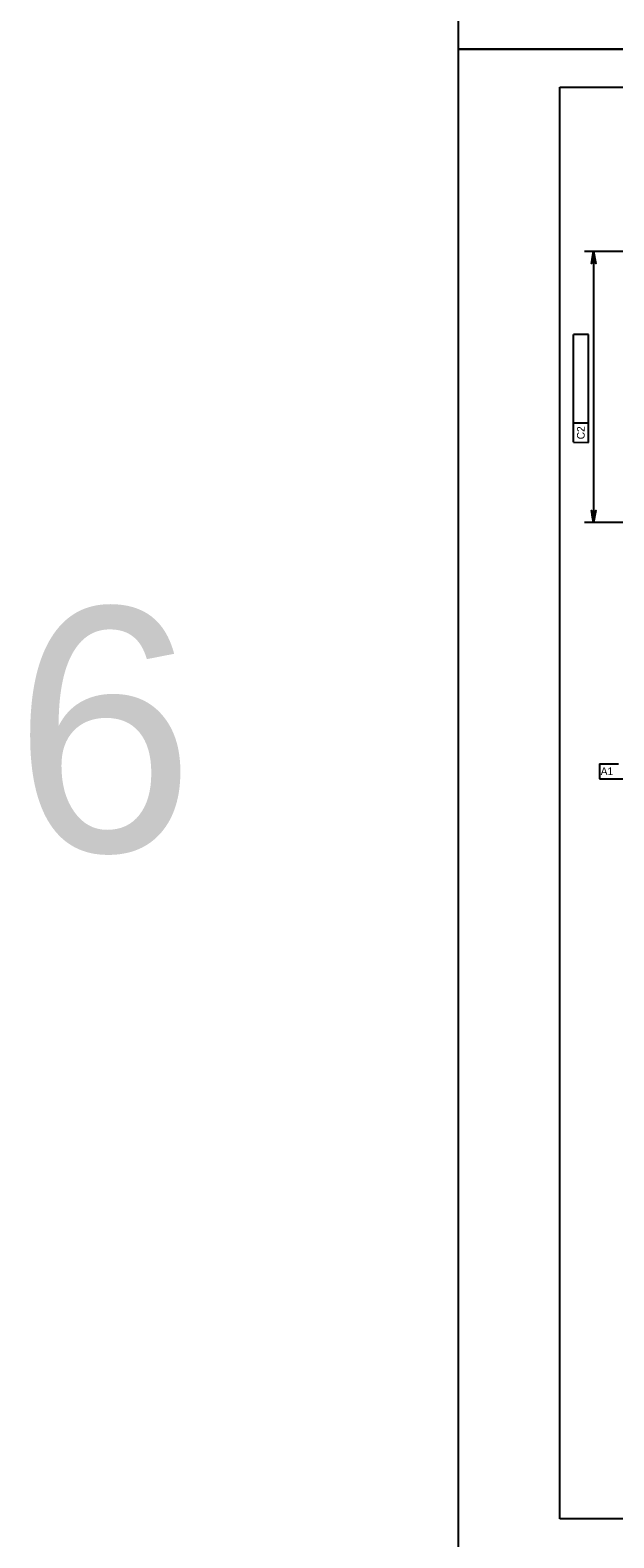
# Model space of a CAD drawing. Extents: x 638263 to 640391, y 293683 to 298655.
# Drawn here: x 638267 to 638497, y 294879 to 295473 of the extents above; entities that cross this region are included whole.
import ezdxf

# ---------------------------------------------------------------- set-up
doc = ezdxf.new("R2010")
doc.units = 0
for name, color, linetype in [('2', 7, 'Continuous'), ('4', 7, 'Continuous'), ('PLT-BNDY', 7, 'Continuous')]:
    doc.layers.add(name, color=color, linetype=linetype)

# ---------------------------------------------------------------- blocks, each defined once
blk = doc.blocks.new('AR')
at = {"layer": '4'}
blk.add_lwpolyline([(5, 0.833375), (5, -0.833375), (0, 0)], close=True, dxfattribs=at)

msp = doc.modelspace()

# ---------------------------------------------------------------- linework, layer by layer
at = {"layer": '2'}
for p, q in [((638475.46, 294886.46), (638475.46, 295450.46)), ((638475.46, 295450.46), (639261.46, 295450.46)), ((639261.46, 294886.46), (638475.46, 294886.46))]:
    msp.add_line(p, q, dxfattribs=at)
at = {"layer": '4'}
for p, q in [((638657.9, 295385.71), (638485.21, 295385.71)), ((638488.72, 295385.71), (638488.72, 295278.98)), ((638486.67, 295353.08), (638480.76, 295353.09)), ((638480.76, 295318.13), (638480.76, 295353.09)), ((638486.67, 295310.56), (638486.67, 295353.08)), ((638480.76, 295310.57), (638480.76, 295318.13)), ((638486.67, 295318.12), (638480.76, 295318.13)), ((638480.76, 295310.57), (638486.67, 295310.56)), ((638598.67, 295278.98), (638485.21, 295278.98)), ((638491.02, 295183.93), (638498.59, 295183.93)), ((638491.02, 295183.93), (638491.02, 295178.03)), ((638491.02, 295178.03), (638533.54, 295178.03))]:
    msp.add_line(p, q, dxfattribs=at)
for points in [[(638488.72, 295385.71), (638489.6, 295381.05), (638489.35, 295381.41), (638489.04, 295381.6), (638488.72, 295381.65), (638488.41, 295381.6), (638488.1, 295381.41), (638487.85, 295381.05), (638488.72, 295385.71), (638488.1, 295381.41), (638488.41, 295381.6), (638488.72, 295385.71), (638488.72, 295381.65), (638489.04, 295381.6), (638488.72, 295385.71), (638489.35, 295381.41)], [(638488.72, 295278.98), (638487.85, 295283.65), (638488.1, 295283.29), (638488.41, 295283.1), (638488.72, 295283.05), (638489.04, 295283.1), (638489.35, 295283.29), (638489.6, 295283.65), (638488.72, 295278.98), (638489.35, 295283.29), (638489.04, 295283.1), (638488.72, 295278.98), (638488.72, 295283.05), (638488.41, 295283.1), (638488.72, 295278.98), (638488.1, 295283.29)]]:
    msp.add_lwpolyline(points, dxfattribs=at)
at = {"layer": 'PLT-BNDY'}
for points in [[(638435.46, 296059.46), (639276.46, 296059.46), (639276.46, 295465.46), (638435.46, 295465.46)], [(638435.46, 295465.46), (639276.46, 295465.46), (639276.46, 294871.46), (638435.46, 294871.46)]]:
    msp.add_lwpolyline(points, close=True, dxfattribs=at)

# ---------------------------------------------------------------- block references
at = {"layer": '4', "xscale": 0.5905511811, "yscale": 0.5905511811}
for p, rotation in [((638488.72, 295385.71), -90.00000000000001), ((638488.72, 295278.98), 90)]:
    msp.add_blockref('AR', p, dxfattribs=dict(at, rotation=rotation))

# ---------------------------------------------------------------- texts
at = {"layer": '4'}
for s, rotation, p in [('C2', 89.93823, (638485.21, 295311.75)), ('A1', 359.93823, (638491.54, 295179.48))]:
    msp.add_text(s, height=3, rotation=rotation, dxfattribs=at).set_placement(p)
msp.add_text('6', height=96, dxfattribs=at).set_placement((638260.07, 295149.38))

doc.saveas('drawing.dxf')
